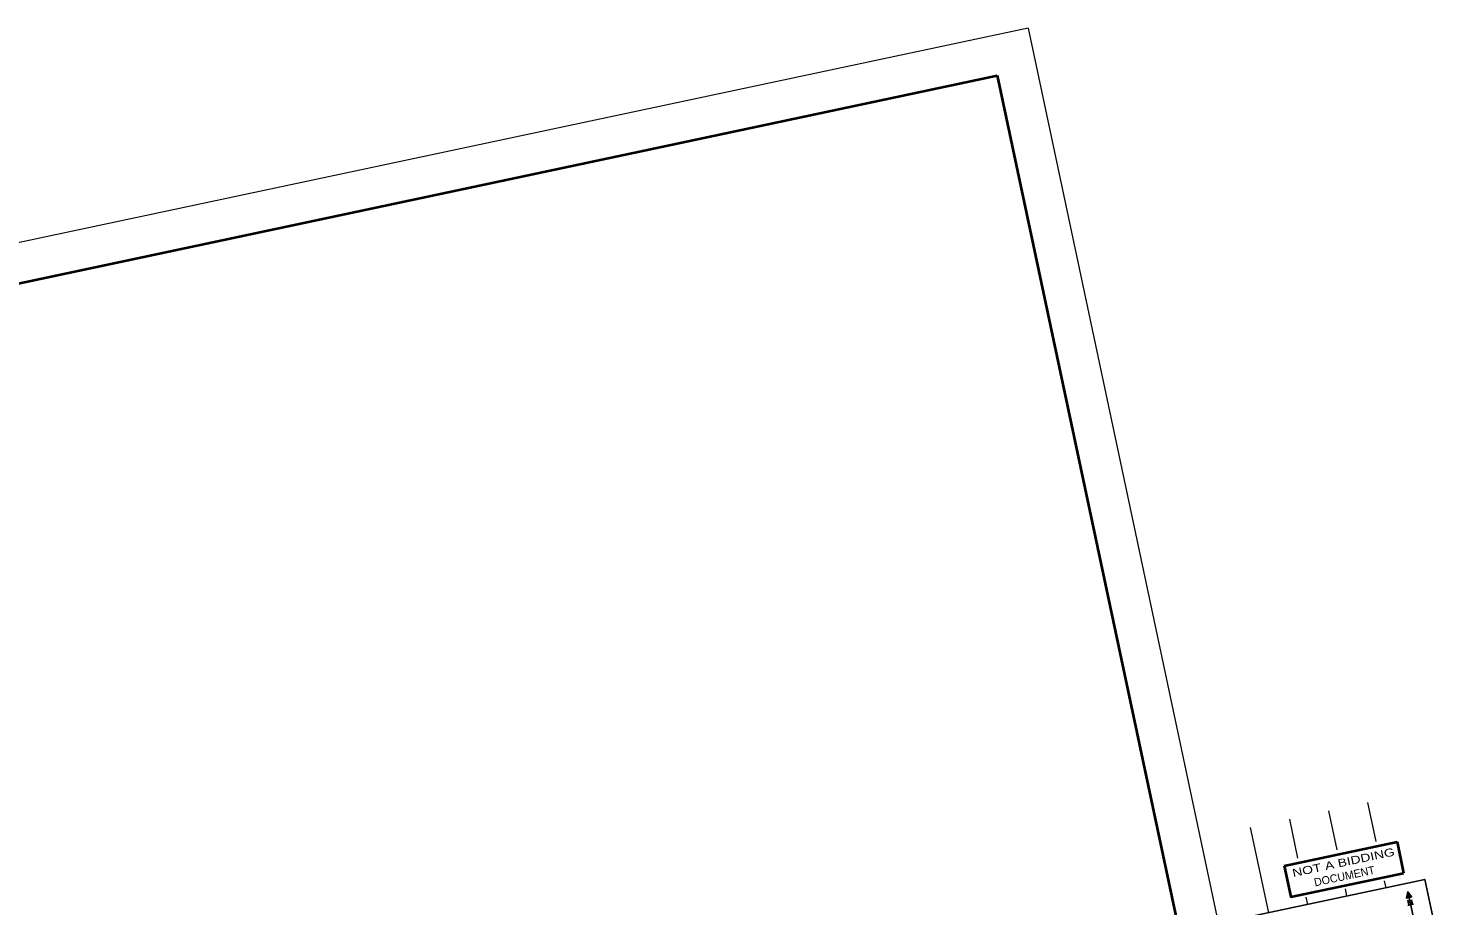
# Model space of a CAD drawing. Extents: x 2357218 to 2371708, y 6973728 to 6980157.
# Drawn here: x 2368095 to 2371611, y 6977962 to 6980157 of the extents above; entities that cross this region are included whole.
import ezdxf
from ezdxf.enums import TextEntityAlignment as Align

# ---------------------------------------------------------------- set-up
doc = ezdxf.new("R2010")
doc.units = 0
doc.header["$LTSCALE"] = 2
for name, color, linetype, lineweight in [('1', 7, 'Continuous', 13), ('44', 7, 'Continuous', 13), ('62', 7, 'Continuous', 13), ('63', 7, 'Continuous', 13)]:
    doc.layers.add(name, color=color, linetype=linetype, lineweight=lineweight)

msp = doc.modelspace()

# ---------------------------------------------------------------- linework, layer by layer
at = {"layer": '1'}
msp.add_line((2370594.559, 6980157.141), (2357291.149, 6977329.415), dxfattribs=at)
at = {"layer": '44'}
msp.add_line((2370594.559, 6980157.141), (2371343.073, 6976635.653), dxfattribs=at)
at = {"layer": '44', "lineweight": 40}
msp.add_line((2370517.53, 6980038.532), (2371224.464, 6976712.679), dxfattribs=at)
msp.add_lwpolyline([(2358116.692, 6973926.537), (2357409.76, 6977252.388), (2370517.53, 6980038.532)], dxfattribs=at)
at = {"layer": '62'}
for p, q in [((2371345.349, 6978199.976), (2371366.141, 6978102.157)), ((2371443.169, 6978220.768), (2371463.961, 6978122.949)), ((2371149.711, 6978158.392), (2371195.063, 6977945.028)), ((2371247.531, 6978179.183), (2371268.323, 6978081.365)), ((2371484.754, 6978025.13), (2371488.521, 6978007.406)), ((2371289.115, 6977983.546), (2371292.882, 6977965.821)), ((2371386.934, 6978004.338), (2371390.701, 6977986.614)), ((2371540.387, 6977981.715), (2371540.373, 6977981.781)), ((2371540.429, 6977982.067), (2371553.04, 6977984.75)), ((2371540.588, 6977982.723), (2371552.65, 6977985.289)), ((2371540.982, 6977981.841), (2371540.689, 6977983.227)), ((2371540.742, 6977983.402), (2371552.255, 6977985.849)), ((2371540.873, 6977984.096), (2371551.834, 6977986.426)), ((2371541.598, 6977981.972), (2371541.015, 6977984.723)), ((2371541.03, 6977984.751), (2371551.442, 6977986.962)), ((2371541.187, 6977985.426), (2371551.047, 6977987.522)), ((2371541.32, 6977986.099), (2371550.63, 6977988.08)), ((2371542.216, 6977982.104), (2371541.349, 6977986.175)), ((2371541.475, 6977986.776), (2371550.234, 6977988.64)), ((2371541.65, 6977987.459), (2371549.839, 6977989.2)), ((2371542.83, 6977982.234), (2371541.675, 6977987.671)), ((2371541.785, 6977988.132), (2371549.444, 6977989.76)), ((2371541.94, 6977988.809), (2371549.049, 6977990.32)), ((2371543.447, 6977982.364), (2371542.01, 6977989.122)), ((2371542.095, 6977989.486), (2371548.633, 6977990.876)), ((2371542.228, 6977990.156), (2371548.237, 6977991.436)), ((2371544.063, 6977982.495), (2371542.337, 6977990.617)), ((2371542.383, 6977990.833), (2371547.821, 6977991.991)), ((2371542.537, 6977991.512), (2371547.426, 6977992.551)), ((2371544.679, 6977982.627), (2371542.668, 6977992.09)), ((2371542.694, 6977992.187), (2371547.007, 6977993.106)), ((2371542.853, 6977992.843), (2371546.617, 6977993.645)), ((2371543.003, 6977993.543), (2371546.219, 6977994.227)), ((2371545.295, 6977982.758), (2371543.003, 6977993.543)), ((2371543.136, 6977994.214), (2371545.822, 6977994.785)), ((2371543.298, 6977994.87), (2371545.434, 6977995.325)), ((2371545.916, 6977982.889), (2371543.331, 6977995.037)), ((2371543.447, 6977995.57), (2371545.032, 6977995.905)), ((2371543.609, 6977996.225), (2371544.62, 6977996.439)), ((2371546.53, 6977983.02), (2371543.667, 6977996.489)), ((2371543.763, 6977996.902), (2371544.225, 6977996.999)), ((2371547.146, 6977983.151), (2371544.19, 6977997.06)), ((2371547.762, 6977983.285), (2371545.105, 6977995.782)), ((2371548.357, 6977983.408), (2371545.999, 6977994.501)), ((2371548.995, 6977983.545), (2371546.932, 6977993.251)), ((2371549.611, 6977983.676), (2371547.847, 6977991.973)), ((2371550.204, 6977983.801), (2371548.737, 6977990.714)), ((2371550.844, 6977983.937), (2371549.674, 6977989.439)), ((2371551.438, 6977984.064), (2371550.568, 6977988.158)), ((2371552.054, 6977984.195), (2371551.479, 6977986.902)), ((2371552.692, 6977984.33), (2371552.416, 6977985.629))]:
    msp.add_line(p, q, dxfattribs=at)
at = {"layer": '62', "lineweight": 40}
for p, q in [((2371234.988, 6978062.123), (2371516.671, 6978121.997)), ((2371516.671, 6978121.997), (2371533.187, 6978044.291))]:
    msp.add_line(p, q, dxfattribs=at)
at = {"layer": '62', "lineweight": 25}
for p, q in [((2371543.804, 6977997.691), (2371556.799, 6977936.546)), ((2371543.327, 6977963.014), (2371557.945, 6977966.121))]:
    msp.add_line(p, q, dxfattribs=at)
at = {"layer": '62', "lineweight": 40}
msp.add_lwpolyline([(2371234.988, 6978062.123), (2371251.504, 6977984.418), (2371533.187, 6978044.291)], dxfattribs=at)
at = {"layer": '62', "lineweight": 25}
for points in [[(2371171.482, 6977817.538), (2371146.576, 6977934.722), (2371586.012, 6978028.129), (2371611.249, 6977911.015)], [(2371543.861, 6977997.406), (2371540.344, 6977981.706), (2371553.263, 6977984.452), (2371543.835, 6977997.538)], [(2371546.042, 6977964.856), (2371543.754, 6977975.618), (2371555.062, 6977966.361), (2371552.69, 6977977.519)]]:
    msp.add_lwpolyline(points, dxfattribs=at)
at = {"layer": '63'}
for p, q in [((2371345.349, 6978199.976), (2371366.141, 6978102.157)), ((2371443.169, 6978220.768), (2371463.961, 6978122.949)), ((2371149.711, 6978158.392), (2371195.063, 6977945.028)), ((2371247.531, 6978179.183), (2371268.323, 6978081.365)), ((2371484.754, 6978025.13), (2371488.521, 6978007.406)), ((2371289.115, 6977983.546), (2371292.882, 6977965.821)), ((2371386.934, 6978004.338), (2371390.701, 6977986.614)), ((2371540.387, 6977981.715), (2371540.373, 6977981.781)), ((2371540.429, 6977982.067), (2371553.04, 6977984.75)), ((2371540.588, 6977982.723), (2371552.65, 6977985.289)), ((2371540.982, 6977981.841), (2371540.689, 6977983.227)), ((2371540.742, 6977983.402), (2371552.255, 6977985.849)), ((2371540.873, 6977984.096), (2371551.834, 6977986.426)), ((2371541.598, 6977981.972), (2371541.015, 6977984.723)), ((2371541.03, 6977984.751), (2371551.442, 6977986.962)), ((2371541.187, 6977985.426), (2371551.047, 6977987.522)), ((2371541.32, 6977986.099), (2371550.63, 6977988.08)), ((2371542.216, 6977982.104), (2371541.349, 6977986.175)), ((2371541.475, 6977986.776), (2371550.234, 6977988.64)), ((2371541.65, 6977987.459), (2371549.839, 6977989.2)), ((2371542.83, 6977982.234), (2371541.675, 6977987.671)), ((2371541.785, 6977988.132), (2371549.444, 6977989.76)), ((2371541.94, 6977988.809), (2371549.049, 6977990.32)), ((2371543.447, 6977982.364), (2371542.01, 6977989.122)), ((2371542.095, 6977989.486), (2371548.633, 6977990.876)), ((2371542.228, 6977990.156), (2371548.237, 6977991.436)), ((2371544.063, 6977982.495), (2371542.337, 6977990.617)), ((2371542.383, 6977990.833), (2371547.821, 6977991.991)), ((2371542.537, 6977991.512), (2371547.426, 6977992.551)), ((2371544.679, 6977982.627), (2371542.668, 6977992.09)), ((2371542.694, 6977992.187), (2371547.007, 6977993.106)), ((2371542.853, 6977992.843), (2371546.617, 6977993.645)), ((2371543.003, 6977993.543), (2371546.219, 6977994.227)), ((2371545.295, 6977982.758), (2371543.003, 6977993.543)), ((2371543.136, 6977994.214), (2371545.822, 6977994.785)), ((2371543.298, 6977994.87), (2371545.434, 6977995.325)), ((2371545.916, 6977982.889), (2371543.331, 6977995.037)), ((2371543.447, 6977995.57), (2371545.032, 6977995.905)), ((2371543.609, 6977996.225), (2371544.62, 6977996.439)), ((2371546.53, 6977983.02), (2371543.667, 6977996.489)), ((2371543.763, 6977996.902), (2371544.225, 6977996.999)), ((2371547.146, 6977983.151), (2371544.19, 6977997.06)), ((2371547.762, 6977983.285), (2371545.105, 6977995.782)), ((2371548.357, 6977983.408), (2371545.999, 6977994.501)), ((2371548.995, 6977983.545), (2371546.932, 6977993.251)), ((2371549.611, 6977983.676), (2371547.847, 6977991.973)), ((2371550.204, 6977983.801), (2371548.737, 6977990.714)), ((2371550.844, 6977983.937), (2371549.674, 6977989.439)), ((2371551.438, 6977984.064), (2371550.568, 6977988.158)), ((2371552.054, 6977984.195), (2371551.479, 6977986.902)), ((2371552.692, 6977984.33), (2371552.416, 6977985.629))]:
    msp.add_line(p, q, dxfattribs=at)
at = {"layer": '63', "lineweight": 40}
for p, q in [((2371234.988, 6978062.123), (2371516.671, 6978121.997)), ((2371516.671, 6978121.997), (2371533.187, 6978044.291))]:
    msp.add_line(p, q, dxfattribs=at)
at = {"layer": '63', "lineweight": 25}
for p, q in [((2371543.804, 6977997.691), (2371556.799, 6977936.546)), ((2371543.327, 6977963.014), (2371557.945, 6977966.121))]:
    msp.add_line(p, q, dxfattribs=at)
at = {"layer": '63', "lineweight": 40}
msp.add_lwpolyline([(2371234.988, 6978062.123), (2371251.504, 6977984.418), (2371533.187, 6978044.291)], dxfattribs=at)
at = {"layer": '63', "lineweight": 25}
for points in [[(2371171.482, 6977817.538), (2371146.576, 6977934.722), (2371586.012, 6978028.129), (2371611.249, 6977911.015)], [(2371543.861, 6977997.406), (2371540.344, 6977981.706), (2371553.263, 6977984.452), (2371543.835, 6977997.538)], [(2371546.042, 6977964.856), (2371543.754, 6977975.618), (2371555.062, 6977966.361), (2371552.69, 6977977.519)]]:
    msp.add_lwpolyline(points, dxfattribs=at)

# ---------------------------------------------------------------- texts
at = {"layer": '62', "width": 1.3}
msp.add_text('NOT A BIDDING', height=20, rotation=12, dxfattribs=at).set_placement((2371384.864, 6978061.197), align=Align.CENTER)
at = {"layer": '62'}
msp.add_text('DOCUMENT', height=20, rotation=12, dxfattribs=at).set_placement((2371387.221, 6978026.731), align=Align.CENTER)
at = {"layer": '63', "width": 1.3}
msp.add_text('NOT A BIDDING', height=20, rotation=12, dxfattribs=at).set_placement((2371384.864, 6978061.197), align=Align.CENTER)
at = {"layer": '63'}
msp.add_text('DOCUMENT', height=20, rotation=12, dxfattribs=at).set_placement((2371387.221, 6978026.731), align=Align.CENTER)

doc.saveas('drawing.dxf')
